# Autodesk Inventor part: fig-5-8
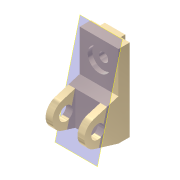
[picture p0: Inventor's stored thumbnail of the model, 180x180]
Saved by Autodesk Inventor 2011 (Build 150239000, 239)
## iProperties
Shininess: 65.0
Angle Display Precision: 2
Document Length Units: 11269
Document Angle Units: 11279
Document Time Units: 11290
Document Mass Units: 11283
Document Length Units Precision: 3
Document Angle Units Precision: 2
Compacted: False
Created: 2001-11
Part Number: fig-5-8
Document SubType Name: Modeling
Designer: Renu Muthoo
Density: 1 g/cm^3
Density: 0.0
Volumn: 0.0
Area: 0.0
PropertySet Name: Model Information
Control State: 0
Master: False
Checked Out: False
Author: Renu Muthoo
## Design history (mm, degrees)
node "Sketch1"
sketch "Sketch2"
  geometry: L1 (33.257, 104.664)-(33.257, -75.336); L2 (33.257, -75.336)-(8.257, -75.336); L3 (8.257, -75.336)-(-45.451, -59.045); L4 (-45.451, -1.628)-(8.257, 14.664); L5 (8.257, 14.664)-(8.257, 104.664); L6 (8.257, 104.664)-(33.257, 104.664); C1 r 15 at (-36.743, -30.336); A1 r 30 centre (-36.743, -30.336) between (-45.451, -1.628) and (-45.451, -59.045)
  constraints: 12 end point, 2 centre point, 2 equal length, 2 parallel, 2 point on circle, 2 tangent, 1 coincident, 1 perpendicular, 1 vertical
  dimensions: "d0" = 180 distance of L1.start L1.end; "d1" = 30 radius of A1; "d2" = 25 distance of L5.end L1.start; "d3" = 45 distance from line of L2 A1.centre; "d4" = 70 distance from line of L1 A1.centre; "d5" = 30 diameter of C1
extrude "Extrusion1" new body sketch "Sketch2" distance "d6" = 85; taper "d7" = 0 deg
workplane "Work Plane1"
sketch "Sketch3"
  geometry: L1 (15, 62.364)-(70, 62.364); L2 (70, 62.364)-(70, -52.386); L3 (70, -52.386)-(15, -52.386); L4 (15, -52.386)-(15, 62.364); L5 (0, -45)-(0, -28.708) reference
  constraints: 8 end point, 2 parallel, 1 horizontal, 1 perpendicular
  dimensions: "d8" = 55 distance of L1.start L1.end; "d9" = 15 distance between parallel lines of L5 L4
extrude "Extrusion2" cut sketch "Sketch3" distance "d10" = 50; taper "d11" = 0 deg
sketch "Sketch4"
  geometry: L1 (0, 25)-(85, 25) reference; L2 (0, 0)-(0, 25) reference; L3 (20, 25)-(65, 25); L4 (65, 25)-(65, 35); L5 (65, 35)-(20, 35); L6 (20, 35)-(20, 25)
  constraints: 8 end point, 2 parallel, 1 horizontal, 1 perpendicular, 1 point on line
  dimensions: "d12" = 45 distance of L4.end L5.end; "d13" = 10 distance of L3.end L4.end; "d14" = 20 distance between parallel lines of L2 L6
extrude "Extrusion3" join sketch "Sketch4" stored distance "d15" = 50; taper "d16" = 0 deg
sketch "Sketch5"
  geometry: L1 (85, 0)-(85, 90) reference; L2 (0, 90)-(85, 90) reference; 1 further point
  dimensions: "d17" = 42 distance from line of L2 point (42.5, 48); "d18" = 42.5 distance from line of L1 point (42.5, 48)
hole "Hole1" sketch "Sketch5" at (42.5, 48) diameter "d19" = 20; stored, may be unused: countersink angle "d23" = 82 deg, drill point angle "d25" = 118 deg; dims "d20" = 6, "d21" = 50, "d22" = 10, "d24" = 8
workplane "Work Plane5"
body "Solid1"
